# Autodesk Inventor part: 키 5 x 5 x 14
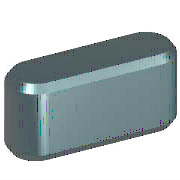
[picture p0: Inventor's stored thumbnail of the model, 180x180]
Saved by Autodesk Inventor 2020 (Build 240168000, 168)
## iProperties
Created: 2012-02
Part Number: 키 5 x 5 x 14
Material: 강철, 연강
Description: 키 및 해당 키홈
Document SubType Name: Modeling
Standard: KS B 1311
Designer: mduedu
Standards Organization: KS
Language: ko-KR
Size Designation: 5 x 5 x 14
Categories: <MemberInstance><Categories><Category DisplayName="샤프트 부품" InternalName="7f7aeb1f-a693-4053-b835-cee3144e0d98" Mnemonic="SHFT"><Category DisplayName="키" Interna
Density: 1 g/cm^3
Appearance: 노란색
IsCustomPart: 1
Author: mduedu
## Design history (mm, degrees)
workplane "Work Plane1"
workplane "Work Plane2"
sketch "스케치1"
  geometry: L1 (2.5, 2.5)-(11.5, 2.5); L2 (11.5, -2.5)-(2.5, -2.5); L3 (0, 9.4)-(0, -7.4) reference; L4 (-5, 0)-(30, 0) reference; L5 (14, 0)-(14, 7); A1 r 2.5 centre (2.5, 0) between (2.5, 2.5) and (2.5, -2.5); A2 r 2.5 centre (11.5, 0) between (11.5, -2.5) and (11.5, 2.5)
  constraints: 6 end point, 5 point on circle, 4 tangent, 3 point on line, 2 centre point, 1 horizontal, 1 parallel, 1 perpendicular
  dimensions: "d0" = 2.5 radius of A1 (= 0.5 x PB); "d13" = 2.5 radius of A2 (= 0.5 x PB); "d14" = 14 distance between parallel lines of L5 L3 (= NLG)
extrude "본체1" new body sketch "스케치1" taper "d3" = 0 deg; stored distance "d4" = 10
workplane "Work Plane3"
body "Solid1"
chamfer "모따기1" distance "d8" = 0.4 (= PHH); stored, may be unused: second distance "d9" = 0.4 (= PHH), angle "d15" = 45 deg
other parameters: "d1" = -3 (= -PNT), "d2" = 2 (= PH - PNT), "NLG" = 14 [user parameter; used in 3 equation terms], "PB" = 5 [user parameter; used in 2 equation terms], "PNT" = 3 [user parameter; used in 2 equation terms], "PH" = 5 [user parameter; used in 1 equation term], "PHH" = 0.4 [user parameter; used in 2 equation terms], "d10" = 0, "d16" = 0, "d17" = 0, "d18" = 0, "WDMIN" = 12 [user parameter], "PLB2" = 14 (= NLG) [user parameter], "WDMAX" = 17 [user parameter], "PLB1" = 14 (= NLG) [user parameter], "RR" = 0.16 [user parameter], "PUEB" = 2.3 [user parameter]
